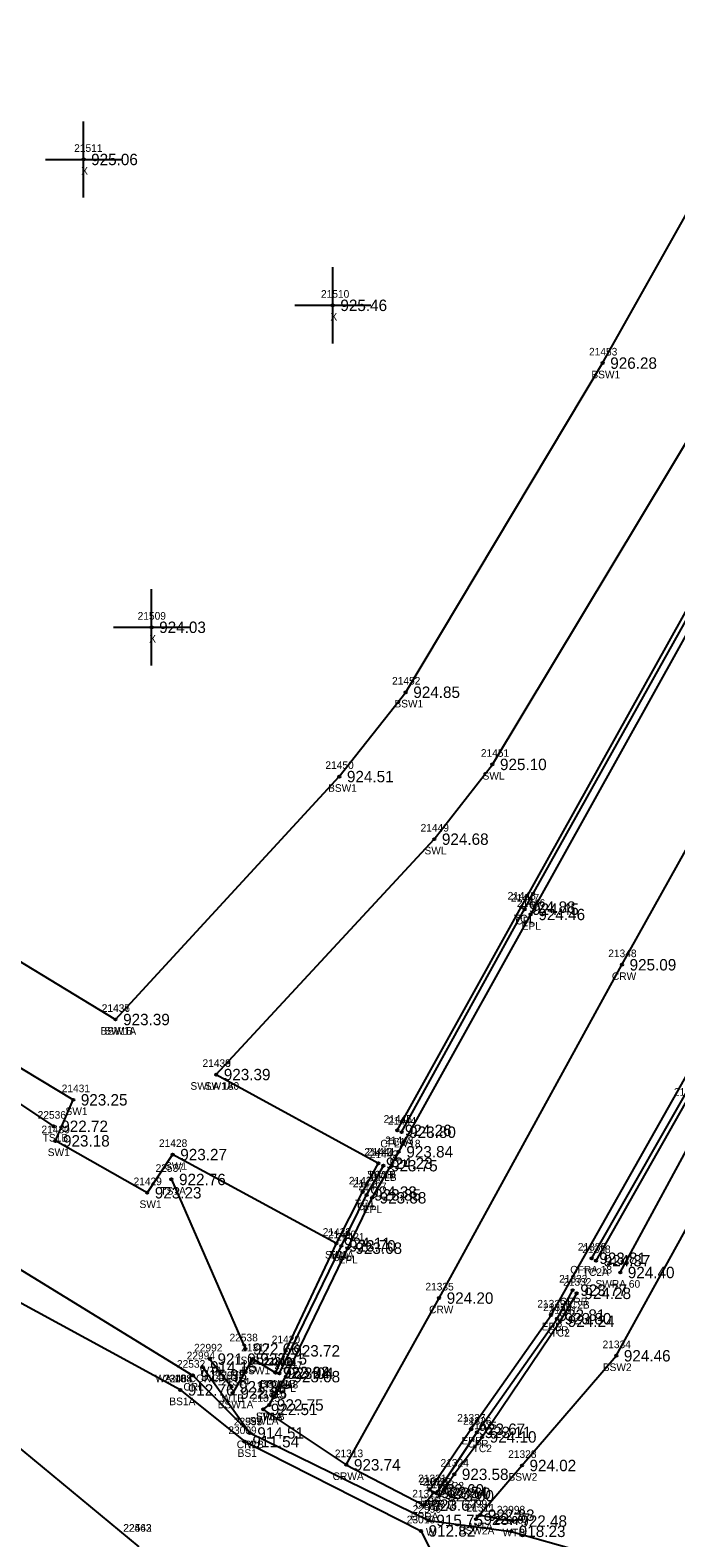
# Model space of a CAD drawing. Extents: x 1576181 to 1577685, y 1099396 to 1101490.
# Drawn here: x 1576866.7 to 1576951.6, y 1100432.1 to 1100630.2 of the extents above; entities that cross this region are included whole.
import ezdxf

# ---------------------------------------------------------------- set-up
doc = ezdxf.new("R2010")
doc.units = 0
for name, color, linetype in [('RD_DTM_BkLn1', 7, 'Continuous'), ('RD_DTM_BkLn2', 7, 'Continuous'), ('RD_DTM_BkLn_txCode', 7, 'Continuous'), ('RD_EX_BldgApp', 7, 'Continuous'), ('RD_EX_Conc', 7, 'Continuous'), ('RD_EX_Conc_txCode', 7, 'Continuous'), ('RD_EX_H2O', 7, 'Continuous'), ('RD_EX_H2O_txCode', 7, 'Continuous'), ('RD_EX_Misc', 7, 'Continuous'), ('RD_EX_Misc_txCode', 7, 'Continuous'), ('RD_EX_Road', 7, 'Continuous'), ('RD_EX_Road_txCode', 7, 'Continuous'), ('RD_EX_TX_Conc_ELEV', 7, 'Continuous'), ('RD_EX_TX_H2O_ELEV', 7, 'Continuous'), ('RD_EX_TX_Misc_ELEV', 7, 'Continuous'), ('RD_EX_TX_Road_ELEV', 7, 'Continuous'), ('RD_HC_Survey_ELEV', 7, 'Continuous'), ('RD_HC_Survey_txCode', 7, 'Continuous'), ('RD_SMD_Locator', 7, 'Continuous')]:
    doc.layers.add(name, color=color, linetype=linetype)

msp = doc.modelspace()

# ---------------------------------------------------------------- linework, layer by layer
at = {"layer": 'RD_DTM_BkLn1'}
msp.add_lwpolyline([(1576908.25, 1100441.74), (1576920.44, 1100463.64), (1576944.47, 1100507.42), (1576973.89, 1100560.12), (1576993.13, 1100594.33), (1577014.77, 1100632.79), (1577042.14, 1100681.68), (1577066.82, 1100725.12), (1577089.75, 1100766.04), (1577111.87, 1100810.02), (1577132.74, 1100857.48), (1577152.58, 1100903.02), (1577172.32, 1100949.02), (1577191.93, 1100994.6), (1577211.77, 1101040.76), (1577222.24, 1101065.99), (1577231.17, 1101086.4), (1577251.41, 1101132.37), (1577271.56, 1101178.18), (1577291.61, 1101224.24), (1577311.77, 1101270.05), (1577333.79, 1101320.46), (1577355.93, 1101371.29), (1577365.01, 1101392.03)], dxfattribs=at)
at = {"layer": 'RD_DTM_BkLn2'}
for p, q in [((1576885.27, 1100479.22), (1576894.98, 1100456.95)), ((1576890.32, 1100455.63), (1576893.16, 1100451.99)), ((1576925.85, 1100435.13), (1576930.11, 1100434.35))]:
    msp.add_line(p, q, dxfattribs=at)
for points in [[(1576914.94, 1100485.67), (1576931.23, 1100514.99), (1576963.09, 1100572.11), (1576979.65, 1100601.9), (1577003.92, 1100645.56), (1577028.33, 1100689.49), (1577054.68, 1100736.79), (1577056.96, 1100744.82), (1577057.69, 1100753.73), (1577056.33, 1100759.1), (1577053.62, 1100754.24)], [(1576886.42, 1100451.57), (1576858.1, 1100466.95), (1576821.38, 1100493.86), (1576777.88, 1100516.88), (1576744.71, 1100544.83), (1576704.93, 1100574.6), (1576655, 1100608.74), (1576614.63, 1100641.39), (1576576.87, 1100675.44), (1576532.94, 1100708.92), (1576490.23, 1100740.56)], [(1576808.73, 1100540.48), (1576834.72, 1100509.46), (1576869.79, 1100486.2)], [(1576941.06, 1100468.55), (1576952.81, 1100489.22), (1576955.87, 1100494.67)], [(1576898.95, 1100453.82), (1576900.28, 1100456.71), (1576906.94, 1100470.82), (1576910.38, 1100477.56), (1576912.46, 1100481.35)], [(1576920.51, 1100437.67), (1576922.43, 1100440.49), (1576926.1, 1100445.4), (1576936.35, 1100460.59), (1576938.53, 1100464.26)], [(1576886.42, 1100451.57), (1576894.91, 1100444.78), (1576918.06, 1100433.05), (1576921.77, 1100425.7)], [(1576897.33, 1100449.02), (1576908.25, 1100441.74), (1576918.43, 1100436.45)]]:
    msp.add_lwpolyline(points, dxfattribs=at)
at = {"layer": 'RD_EX_BldgApp'}
msp.add_lwpolyline([(1576889.35, 1100454.59), (1576895.55, 1100445.92), (1576919.08, 1100434.44), (1576929.91, 1100433)], dxfattribs=at)
at = {"layer": 'RD_EX_Conc'}
for p, q in [((1576940.49, 1100468.87), (1576955.37, 1100494.89)), ((1576891.15, 1100493), (1576912.46, 1100481.35)), ((1576897.33, 1100449.02), (1576898.13, 1100449.6))]:
    msp.add_line(p, q, dxfattribs=at)
for points in [[(1576915.51, 1100485.43), (1576931.67, 1100514.72), (1576963.55, 1100571.7), (1576980.25, 1100601.73), (1577004.87, 1100645.93), (1577028.8, 1100689.21), (1577055.24, 1100736.45), (1577057.45, 1100744.79), (1577058.3, 1100753.83), (1577056.52, 1100760.31), (1577053.21, 1100754.37)], [(1576891.15, 1100493), (1576919.81, 1100523.92), (1576927.44, 1100533.74), (1576954.89, 1100579.32), (1576970.59, 1100607.1), (1576994.86, 1100650.35), (1577020.05, 1100695.25), (1577043.02, 1100736.52), (1577053.21, 1100754.37)], [(1576877.92, 1100500.23), (1576907.33, 1100532.14), (1576916.05, 1100543.22), (1576941.93, 1100586.45), (1576957.84, 1100614.79), (1576982.46, 1100658.75), (1577007.42, 1100703.25), (1577021.88, 1100729.08)], [(1576925.28, 1100434.6), (1576931.32, 1100441.65), (1576943.72, 1100456.06), (1576959.8, 1100485.15), (1576962.79, 1100490.55), (1576976.91, 1100516.3), (1576979.99, 1100521.81), (1576994.08, 1100547.41), (1577013.9, 1100582.65), (1577028.01, 1100607.52), (1577031.93, 1100618.57), (1577033.8, 1100624.22), (1577052.4, 1100657.66), (1577055.15, 1100662.64), (1577085.17, 1100716.01)], [(1576838.26, 1100530.43), (1576857.4, 1100512.67), (1576877.92, 1100500.23)], [(1576906.94, 1100470.82), (1576885.43, 1100482.49), (1576882.08, 1100477.47), (1576870.02, 1100484.29), (1576872.36, 1100489.68), (1576850.65, 1100502.77), (1576830.64, 1100520.82)], [(1576944.24, 1100467), (1576955.49, 1100487.77), (1576955.87, 1100494.67)], [(1576899.45, 1100453.77), (1576907.61, 1100470.5), (1576910.91, 1100477.19), (1576913.12, 1100481.03)], [(1576920.1, 1100437.99), (1576925.42, 1100446), (1576935.94, 1100460.93), (1576938, 1100464.68)], [(1576893.32, 1100451.16), (1576895.95, 1100455.64), (1576898.9, 1100453.88)]]:
    msp.add_lwpolyline(points, dxfattribs=at)
at = {"layer": 'RD_EX_H2O'}
for points in [[(1576494.39, 1100746.79), (1576534.48, 1100716.7), (1576580.85, 1100681.51), (1576619.55, 1100647.19), (1576656.92, 1100617.1), (1576703.9, 1100584.73), (1576745.77, 1100553.17), (1576784.85, 1100522.68), (1576823.53, 1100500.6), (1576858.62, 1100471.57), (1576888.07, 1100453.49), (1576895.55, 1100445.92)], [(1576881.04, 1100430.95), (1576850.51, 1100456.18), (1576811.02, 1100474.55), (1576770.3, 1100506.51), (1576738.8, 1100537.68), (1576691.12, 1100558.51), (1576645.69, 1100592.61), (1576611.01, 1100637.34), (1576572.36, 1100669.07), (1576520.62, 1100693.32), (1576482.36, 1100733.93)], [(1576929.91, 1100433), (1576951.7, 1100426.83), (1576996.53, 1100400.27), (1577038.81, 1100373.75), (1577079.67, 1100350.15), (1577122.69, 1100322.64), (1577157.62, 1100301.09), (1577195.23, 1100276.28), (1577240.04, 1100251.66), (1577278.94, 1100221.51), (1577312.77, 1100200.12), (1577352.78, 1100176.91)]]:
    msp.add_lwpolyline(points, dxfattribs=at)
at = {"layer": 'RD_EX_Misc'}
for p, q in [((1576873.72, 1100608.2), (1576873.72, 1100618.2)), ((1576868.72, 1100613.2), (1576878.72, 1100613.2)), ((1576906.47, 1100589.04), (1576906.47, 1100599.04)), ((1576901.47, 1100594.04), (1576911.47, 1100594.04)), ((1576882.66, 1100546.75), (1576882.66, 1100556.75)), ((1576877.66, 1100551.75), (1576887.66, 1100551.75))]:
    msp.add_line(p, q, dxfattribs=at)
at = {"layer": 'RD_EX_Road'}
for points in [[(1576898.13, 1100449.6), (1576900.3, 1100453.32), (1576908.44, 1100470.19), (1576911.63, 1100476.81), (1576915.14, 1100482.86), (1576932.49, 1100514.03), (1576964.32, 1100571.23), (1576981.09, 1100601.29), (1577005.14, 1100644.55), (1577029.51, 1100688.7), (1577055.93, 1100735.94), (1577058.21, 1100744.65), (1577059.15, 1100754.07), (1577057.45, 1100760.72), (1577053.13, 1100767.88), (1577044.53, 1100776.69), (1577044.53, 1100776.69), (1577000.54, 1100813.12)], [(1576918.43, 1100436.45), (1576919.69, 1100438.1), (1576919.21, 1100438.45), (1576924.62, 1100446.41), (1576935.15, 1100461.4), (1576954.41, 1100495.42), (1576968.8, 1100521.52), (1576985.92, 1100552.3), (1577005.62, 1100587.42), (1577028.14, 1100627.58), (1577046.67, 1100660.87), (1577078.76, 1100718.33)]]:
    msp.add_lwpolyline(points, dxfattribs=at)
at = {"layer": 'RD_SMD_Locator'}
for centre in [(1576873.72, 1100613.2), (1576906.47, 1100594.04), (1576941.93, 1100586.45), (1576882.66, 1100551.75), (1576916.05, 1100543.22), (1576927.44, 1100533.74), (1576907.33, 1100532.14), (1576919.81, 1100523.92), (1576931.23, 1100514.99), (1576931.67, 1100514.72), (1576932.49, 1100514.03), (1576944.47, 1100507.42), (1576877.92, 1100500.23), (1576877.92, 1100500.23), (1576891.15, 1100493), (1576891.15, 1100493), (1576872.36, 1100489.68), (1576869.79, 1100486.2), (1576914.94, 1100485.67), (1576915.51, 1100485.43), (1576870.02, 1100484.29), (1576915.14, 1100482.86), (1576885.43, 1100482.49), (1576912.46, 1100481.35), (1576912.46, 1100481.35), (1576913.12, 1100481.03), (1576885.27, 1100479.22), (1576882.08, 1100477.47), (1576910.38, 1100477.56), (1576910.91, 1100477.19), (1576911.63, 1100476.81), (1576906.94, 1100470.82), (1576906.94, 1100470.82), (1576907.61, 1100470.5), (1576908.44, 1100470.19), (1576940.49, 1100468.87), (1576941.06, 1100468.55), (1576944.24, 1100467), (1576920.44, 1100463.64), (1576938, 1100464.68), (1576938.53, 1100464.26), (1576935.15, 1100461.4), (1576935.94, 1100460.93), (1576936.35, 1100460.59), (1576890.32, 1100455.63), (1576894.98, 1100456.95), (1576895.95, 1100455.64), (1576900.28, 1100456.71), (1576943.72, 1100456.06), (1576888.07, 1100453.49), (1576889.35, 1100454.59), (1576898.9, 1100453.88), (1576898.95, 1100453.82), (1576899.45, 1100453.77), (1576900.3, 1100453.32), (1576886.42, 1100451.57), (1576886.42, 1100451.57), (1576893.16, 1100451.99), (1576893.32, 1100451.16), (1576898.13, 1100449.6), (1576898.13, 1100449.6), (1576897.33, 1100449.02), (1576895.55, 1100445.92), (1576895.55, 1100445.92), (1576924.62, 1100446.41), (1576925.42, 1100446), (1576926.1, 1100445.4), (1576894.91, 1100444.78), (1576908.25, 1100441.74), (1576931.32, 1100441.65), (1576922.43, 1100440.49), (1576919.21, 1100438.45), (1576919.69, 1100438.1), (1576920.1, 1100437.99), (1576920.51, 1100437.67), (1576918.43, 1100436.45), (1576919.08, 1100434.44), (1576925.28, 1100434.6), (1576925.85, 1100435.13), (1576930.11, 1100434.35), (1576918.06, 1100433.05), (1576929.91, 1100433), (1576929.91, 1100433)]:
    msp.add_circle(centre, 0.15, dxfattribs=at)

# ---------------------------------------------------------------- texts
at = {"layer": 'RD_DTM_BkLn_txCode'}
for s, p in [('22536', (1576867.69, 1100487.2)), ('TS1B', (1576868.35, 1100484.2)), ('22537', (1576883.19, 1100480.22)), ('TS1A', (1576883.82, 1100477.22)), ('22538', (1576892.9, 1100457.95)), ('TS1B', (1576893.54, 1100454.95)), ('23008', (1576884.26, 1100452.57)), ('22464', (1576884.32, 1100452.57)), ('BS1A', (1576884.99, 1100449.57)), ('BS1A', (1576884.99, 1100449.57)), ('23009', (1576892.75, 1100445.78)), ('BS1', (1576893.97, 1100442.78)), ('23010', (1576916.19, 1100434.05))]:
    msp.add_text(s, height=1, dxfattribs=at).set_placement(p)
at = {"layer": 'RD_EX_Conc_txCode'}
for s, p in [('21453', (1576940.14, 1100587.45)), ('BSW1', (1576940.45, 1100584.45)), ('21452', (1576914.26, 1100544.22)), ('BSW1', (1576914.57, 1100541.22)), ('21451', (1576925.93, 1100534.74)), ('21450', (1576905.5, 1100533.14)), ('SWL', (1576926.15, 1100531.74)), ('BSW1', (1576905.85, 1100530.14)), ('21449', (1576918.01, 1100524.92)), ('SWL', (1576918.52, 1100521.92)), ('21448', (1576929.44, 1100515.99)), ('21447', (1576929.88, 1100515.72)), ('TC1', (1576930.27, 1100512.99)), ('CFL', (1576930.47, 1100512.72)), ('21436', (1576876.1, 1100501.23)), ('21437', (1576876.12, 1100501.23)), ('BSW1A', (1576875.95, 1100498.23)), ('SW1B', (1576876.44, 1100498.23)), ('21438', (1576889.35, 1100494)), ('21439', (1576889.35, 1100494)), ('21431', (1576870.85, 1100490.68)), ('SWLA 180', (1576887.77, 1100491)), ('SW1A', (1576889.65, 1100491)), ('21341', (1576951.3, 1100490.22)), ('SW1', (1576871.35, 1100487.68)), ('21445', (1576913.15, 1100486.67)), ('21444', (1576913.72, 1100486.43)), ('21430', (1576868.19, 1100485.29)), ('SW1', (1576869.01, 1100482.29)), ('21428', (1576883.63, 1100483.49)), ('21440', (1576910.62, 1100482.35)), ('21441', (1576910.95, 1100482.35)), ('21442', (1576911.33, 1100482.03)), ('CFLA 18', (1576912.72, 1100483.43)), ('TC1A', (1576913.49, 1100483.67)), ('SW1', (1576884.42, 1100480.49)), ('21429', (1576880.29, 1100478.47)), ('21425', (1576908.58, 1100478.56)), ('21426', (1576909.09, 1100478.19)), ('SW1B', (1576910.98, 1100479.35)), ('TC1B', (1576911.03, 1100479.35)), ('CFLB', (1576911.44, 1100479.03)), ('SW1', (1576881.08, 1100475.47)), ('TC1', (1576909.41, 1100475.56)), ('CFL', (1576909.71, 1100475.19)), ('21423', (1576905.15, 1100471.82)), ('21424', (1576905.15, 1100471.82)), ('21422', (1576905.82, 1100471.5)), ('SW1A', (1576905.45, 1100468.82)), ('TC1', (1576905.98, 1100468.82)), ('CFL', (1576906.41, 1100468.5)), ('21336', (1576938.67, 1100469.87)), ('21338', (1576939.26, 1100469.55)), ('21337', (1576942.45, 1100468)), ('CFRA 18', (1576937.67, 1100466.87)), ('TC2A', (1576939.32, 1100466.55)), ('21333', (1576936.21, 1100465.68)), ('21332', (1576936.74, 1100465.26)), ('SWRA 60', (1576940.99, 1100465)), ('CFRB', (1576936.3, 1100462.68)), ('TC2B', (1576936.81, 1100462.26)), ('21330', (1576934.11, 1100461.93)), ('21331', (1576934.84, 1100461.59)), ('CFR', (1576934.71, 1100458.93)), ('TC2', (1576935.1, 1100458.59)), ('21317', (1576894.44, 1100456.64)), ('21420', (1576898.45, 1100457.71)), ('21334', (1576941.92, 1100457.06)), ('21318', (1576897.39, 1100454.88)), ('21419', (1576897.44, 1100454.82)), ('21418', (1576897.93, 1100454.77)), ('TC1', (1576899.32, 1100454.71)), ('21314', (1576891.81, 1100452.16)), ('BSW1', (1576894.47, 1100453.64)), ('BSW2', (1576941.95, 1100454.06)), ('21316', (1576896.59, 1100450.6)), ('CFLA 18', (1576896.65, 1100451.77)), ('BSW1B', (1576896.95, 1100451.88)), ('TC1A', (1576897.5, 1100451.82)), ('BSW1A', (1576891.35, 1100449.16)), ('21315', (1576895.82, 1100450.02)), ('SWLA', (1576895.55, 1100447.02)), ('SWLB', (1576896.36, 1100447.6)), ('21326', (1576923.6, 1100447)), ('21325', (1576924.3, 1100446.4)), ('CFR', (1576924.19, 1100444)), ('TC2', (1576924.85, 1100443.4)), ('21328', (1576929.52, 1100442.65)), ('21324', (1576920.63, 1100441.49)), ('21322', (1576918.31, 1100438.99)), ('21323', (1576918.72, 1100438.67)), ('TC2', (1576921.19, 1100438.49)), ('BSW2', (1576929.56, 1100439.65)), ('CFRA 18', (1576917.28, 1100435.99)), ('TC2A', (1576918.78, 1100435.67)), ('21311', (1576924.05, 1100435.6)), ('BSW2A', (1576923.02, 1100432.6))]:
    msp.add_text(s, height=1, dxfattribs=at).set_placement(p)
at = {"layer": 'RD_EX_H2O_txCode'}
for s, p in [('22532', (1576885.99, 1100454.49)), ('CRL', (1576886.84, 1100451.49)), ('22533', (1576893.47, 1100446.92)), ('CRLB', (1576893.85, 1100443.92)), ('22463', (1576878.93, 1100432.95)), ('22542', (1576878.96, 1100432.95)), ('22606', (1576927.74, 1100434))]:
    msp.add_text(s, height=1, dxfattribs=at).set_placement(p)
at = {"layer": 'RD_EX_Misc_txCode'}
for s, p in [('21511', (1576872.49, 1100614.2)), ('X', (1576873.41, 1100611.2)), ('21510', (1576904.92, 1100595.04)), ('X', (1576906.16, 1100592.04)), ('21509', (1576880.83, 1100552.75)), ('X', (1576882.35, 1100549.75)), ('22992', (1576888.25, 1100456.63)), ('22994', (1576887.27, 1100455.59)), ('WA 18 CONCRETE', (1576883.15, 1100452.59)), ('WTA', (1576888.98, 1100453.63)), ('22993', (1576891.08, 1100452.99)), ('WTB', (1576891.83, 1100449.99)), ('22995', (1576893.47, 1100446.92)), ('W', (1576895.18, 1100443.92)), ('22996', (1576916.97, 1100435.44)), ('22997', (1576923.78, 1100436.13)), ('22998', (1576928.03, 1100435.35)), ('W', (1576918.71, 1100432.44)), ('WTA', (1576924.51, 1100433.13)), ('22999', (1576927.83, 1100434)), ('WTB', (1576928.78, 1100432.35))]:
    msp.add_text(s, height=1, dxfattribs=at).set_placement(p)
at = {"layer": 'RD_EX_Road_txCode'}
for s, p in [('21446', (1576930.67, 1100515.03)), ('EPL', (1576931.29, 1100512.03)), ('21443', (1576913.35, 1100483.86)), ('EPL', (1576913.94, 1100480.86)), ('21427', (1576909.83, 1100477.81)), ('EPL', (1576910.42, 1100474.81)), ('21421', (1576906.93, 1100471.19)), ('EPL', (1576907.23, 1100468.19)), ('21329', (1576933.35, 1100462.4)), ('EPR', (1576933.92, 1100459.4)), ('21417', (1576898.79, 1100454.32)), ('21416', (1576896.59, 1100450.6)), ('EPL', (1576899.09, 1100451.32)), ('EPLA', (1576896.43, 1100447.6)), ('21327', (1576922.82, 1100447.41)), ('EPR', (1576923.39, 1100444.41)), ('21321', (1576917.69, 1100439.45)), ('21320', (1576917.85, 1100439.1)), ('21319', (1576916.91, 1100437.45)), ('EPR', (1576917.98, 1100436.45)), ('EPRA', (1576916.71, 1100434.45)), ('EPR', (1576918.46, 1100436.1))]:
    msp.add_text(s, height=1, dxfattribs=at).set_placement(p)
at = {"layer": 'RD_EX_TX_Conc_ELEV'}
for s, p in [('926.28', (1576942.93, 1100585.7)), ('924.85', (1576917.05, 1100542.47)), ('925.10', (1576928.44, 1100532.99)), ('924.51', (1576908.33, 1100531.39)), ('924.68', (1576920.81, 1100523.17)), ('924.88', (1576932.23, 1100514.24)), ('924.45', (1576932.67, 1100513.97)), ('923.39', (1576878.92, 1100499.48)), ('923.39', (1576878.92, 1100499.48)), ('923.39', (1576892.15, 1100492.25)), ('923.39', (1576892.15, 1100492.25)), ('923.25', (1576873.36, 1100488.93)), ('923.18', (1576871.02, 1100483.54)), ('924.26', (1576915.94, 1100484.92)), ('923.80', (1576916.51, 1100484.68)), ('923.27', (1576886.43, 1100481.74)), ('924.23', (1576913.46, 1100480.6)), ('924.23', (1576913.46, 1100480.6)), ('923.75', (1576914.12, 1100480.28)), ('923.23', (1576883.08, 1100476.72)), ('924.33', (1576911.38, 1100476.81)), ('923.85', (1576911.91, 1100476.44)), ('924.11', (1576907.94, 1100470.07)), ('924.11', (1576907.94, 1100470.07)), ('923.70', (1576908.61, 1100469.75)), ('923.81', (1576941.49, 1100468.12)), ('924.37', (1576942.06, 1100467.8)), ('924.40', (1576945.24, 1100466.25)), ('923.77', (1576939, 1100463.93)), ('924.28', (1576939.53, 1100463.51)), ('923.80', (1576936.94, 1100460.18)), ('924.24', (1576937.35, 1100459.84)), ('923.72', (1576901.28, 1100455.96)), ('922.75', (1576896.95, 1100454.89)), ('924.46', (1576944.72, 1100455.31)), ('922.92', (1576899.9, 1100453.13)), ('923.04', (1576899.95, 1100453.07)), ('923.04', (1576900.45, 1100453.02)), ('922.35', (1576894.32, 1100450.41)), ('922.51', (1576898.33, 1100448.27)), ('922.75', (1576899.13, 1100448.85)), ('923.11', (1576926.42, 1100445.25)), ('924.10', (1576927.1, 1100444.65)), ('924.02', (1576932.32, 1100440.9)), ('923.58', (1576923.43, 1100439.74)), ('923.60', (1576921.1, 1100437.24)), ('923.60', (1576921.51, 1100436.92)), ('923.77', (1576926.28, 1100433.85))]:
    msp.add_text(s, height=1.5, dxfattribs=at).set_placement(p)
at = {"layer": 'RD_EX_TX_H2O_ELEV'}
for s, p in [('915.85', (1576889.07, 1100452.74)), ('914.51', (1576896.55, 1100445.17)), ('918.23', (1576930.91, 1100432.25))]:
    msp.add_text(s, height=1.5, dxfattribs=at).set_placement(p)
at = {"layer": 'RD_EX_TX_Misc_ELEV'}
for s, p in [('925.06', (1576874.72, 1100612.45)), ('925.46', (1576907.47, 1100593.29)), ('924.03', (1576883.66, 1100551)), ('922.72', (1576870.79, 1100485.45)), ('922.76', (1576886.27, 1100478.47)), ('922.66', (1576895.98, 1100456.2)), ('914.15', (1576890.35, 1100453.84)), ('921.05', (1576891.32, 1100454.88)), ('912.76', (1576887.42, 1100450.82)), ('912.76', (1576887.42, 1100450.82)), ('921.38', (1576894.16, 1100451.24)), ('911.54', (1576895.91, 1100444.03)), ('914.51', (1576896.55, 1100445.17)), ('922.83', (1576926.85, 1100434.38)), ('912.82', (1576919.06, 1100432.3)), ('915.75', (1576920.08, 1100433.69)), ('918.23', (1576930.91, 1100432.25)), ('922.48', (1576931.11, 1100433.6))]:
    msp.add_text(s, height=1.5, dxfattribs=at).set_placement(p)
at = {"layer": 'RD_EX_TX_Road_ELEV'}
for s, p in [('924.46', (1576933.49, 1100513.28)), ('923.84', (1576916.14, 1100482.11)), ('923.88', (1576912.63, 1100476.06)), ('923.68', (1576909.44, 1100469.44)), ('923.81', (1576936.15, 1100460.65)), ('923.08', (1576901.3, 1100452.57)), ('922.75', (1576899.13, 1100448.85)), ('923.67', (1576925.62, 1100445.66)), ('923.60', (1576920.21, 1100437.7)), ('923.54', (1576920.69, 1100437.35)), ('923.67', (1576919.43, 1100435.7))]:
    msp.add_text(s, height=1.5, dxfattribs=at).set_placement(p)
at = {"layer": 'RD_HC_Survey_ELEV'}
for s, p in [('925.09', (1576945.47, 1100506.67)), ('924.20', (1576921.44, 1100462.89)), ('923.74', (1576909.25, 1100440.99))]:
    msp.add_text(s, height=1.5, dxfattribs=at).set_placement(p)
at = {"layer": 'RD_HC_Survey_txCode'}
for s, p in [('21348', (1576942.67, 1100508.42)), ('CRW', (1576943.15, 1100505.42)), ('21335', (1576918.64, 1100464.64)), ('CRW', (1576919.12, 1100461.64)), ('21313', (1576906.74, 1100442.74)), ('CRWA', (1576906.45, 1100439.74))]:
    msp.add_text(s, height=1, dxfattribs=at).set_placement(p)

doc.saveas('drawing.dxf')
